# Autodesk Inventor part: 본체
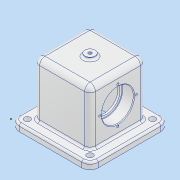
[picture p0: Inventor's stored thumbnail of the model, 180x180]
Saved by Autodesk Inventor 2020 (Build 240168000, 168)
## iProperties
Created: 2022-07
Part Number: 본체
Material: 알루미늄 6061
Document SubType Name: Modeling
Designer: MIRAE
Density: 2.7 g/cm^3
Appearance: 알루미늄 - 평지
Mass: 1059.83 g
Surface Area: 721.846 cm^2
Volume: 392.53 cm^3
Author: MIRAE
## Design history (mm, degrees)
sketch "스케치1"
  geometry: L1 (0, 0)-(-116, 0); L2 (-116, 0)-(-116, -116); L3 (-116, -116)-(0, -116); L4 (0, -116)-(0, 0)
  constraints: 8 end point, 2 parallel, 1 horizontal, 1 perpendicular
  dimensions: "d0" = 116 distance of L2.end L3.end; "d1" = 116 distance of L1.end L2.end
extrude "돌출1" new body sketch "스케치1" distance "d2" = 10; taper "d3" = 0 deg
sketch "스케치2"
  geometry: L1 (0, 116)-(0, 0) reference; L2 (0, 58)-(116, 58) reference; L3 (116, 0)-(116, 116) reference; L4 (58, 116)-(58, 0) reference; L5 (17, 99)-(99, 99); L6 (99, 99)-(99, 17); L7 (99, 17)-(17, 17); L8 (17, 17)-(17, 99); L9 (17, 99)-(99, 17); L10 (99, 99)-(17, 17); 2 further points
  constraints: 16 end point, 6 midpoint, 2 horizontal, 2 parallel, 2 vertical, 1 perpendicular, 1 other
  dimensions: "d4" = 82 distance of L5.start L5.end; "d5" = 82 distance of L5.end L6.end
extrude "돌출2" join sketch "스케치2" distance "d6" = 80; taper "d7" = 0 deg
sketch "스케치3"
  geometry: L1 (116, -116)-(0, -116) reference; L2 (58, -116)-(58, 0) reference; L3 (0, 0)-(116, 0) reference; L4 (116, -58)-(0, -58) reference; L5 (79, -88)-(37, -88); L6 (37, -88)-(37, -28); L7 (37, -28)-(79, -28); L8 (79, -28)-(79, -88); L9 (79, -88)-(37, -28); L10 (37, -88)-(79, -28); 2 further points
  constraints: 16 end point, 6 midpoint, 3 horizontal, 2 parallel, 1 perpendicular, 1 vertical, 1 other
  dimensions: "d8" = 42 distance of L5.start L5.end; "d9" = 60 distance of L5.end L6.end
extrude "돌출3" cut sketch "스케치3" distance "d10" = 80; taper "d11" = 0 deg
node "작업 평면1"
sketch "스케치4"
  geometry: L1 (17, 10)-(17, 90); L2 (0, 0)-(116, 0) reference; L3 (17, 48)-(99, 48); L4 (99, 10)-(99, 90); L5 (17, 48)-(34, 48); L6 (34, 48)-(34, 71.5); L7 (34, 71.5)-(17, 71.5); L8 (17, 71.5)-(17, 48); L9 (34, 48)-(38.895, 48); L10 (34, 67.956)-(34, 48); L11 (37, 0)-(37, 80) reference; L12 (34, 48)-(37, 48); L13 (37, 48)-(37, 68); L14 (37, 68)-(34, 68); L15 (34, 68)-(34, 48); L16 (79, 80)-(37, 80) reference; L17 (58, 80)-(58, 48); L18 (82, 71.5)-(99, 71.5); L19 (82, 67.956)-(82, 48); L20 (82, 48)-(82, 71.5); L21 (79, 68)-(82, 68); L22 (79, 0)-(79, 80); 6 further points
  constraints: 38 end point, 7 symmetric about line, 4 point on line, 2 horizontal, 2 midpoint, 2 parallel, 1 perpendicular
  dimensions: "d14" = 48 distance between parallel lines of L2 L3; "d15" = 17 distance of L6.end L7.end; "d17" = 40 diameter of L14 L3; "d18" = 47 diameter of L7 L3
revolve "회전1" sketch "스케치4" stored, may be unused: angle "d19" = 90 deg
fillet "모깎기1" dims "d20" = 8
fillet "모깎기2" dims "d21" = 8
chamfer "모따기1" distance "d22" = 1; stored, may be unused: second distance "d23" = 2, angle "d24" = 45 deg
chamfer "모따기2" distance "d25" = 1; stored, may be unused: second distance "d26" = 2, angle "d27" = 45 deg
sketch "스케치5" dims "d28" = 54
  geometry: C1 r 20 at (33, 38) reference; 3 further points
  constraints: 1 coincident, 1 vertical alignment, 2 other
hole "구멍1" sketch "스케치5" at (33, 65) diameter "d29" = 3.242; stored, may be unused: countersink angle "d33" = 90 deg, drill point angle "d35" = 118 deg; dims "d30" = 8, "d31" = 4, "d32" = 2, "d34" = 10
node "작업 평면2"
sketch "스케치6"
  geometry: 1 further point
fillet "모깎기3" dims "d40" = 12
sketch "스케치7"
  geometry: A1 r 12 centre (12, 12) between (0, 12) and (12, 0) reference; A2 r 12 centre (12, 104) between (12, 116) and (0, 104) reference; A3 r 12 centre (104, 104) between (116, 104) and (104, 116) reference; A4 r 12 centre (104, 12) between (104, 0) and (116, 12) reference; 5 further points
  constraints: 4 coincident
hole "구멍2" sketch "스케치7" at (12, 12), (12, 104), (104, 104), (104, 12) diameter "d41" = 9; stored, may be unused: countersink angle "d45" = 90 deg, drill point angle "d47" = 0 deg; dims "d42" = 8, "d43" = 4, "d44" = 2, "d46" = 10
sketch "스케치8"
  geometry: L1 (25, 17)-(91, 17) reference; L2 (58, 17)-(58, 99); L3 (91, 99)-(25, 99) reference; C1 r 7.5 at (58, 58); 1 further point
  constraints: 3 midpoint, 2 end point, 1 centre point
  dimensions: "d48" = 15 diameter of C1
extrude "돌출4" join sketch "스케치8" distance "d49" = 4; taper "d50" = 0 deg
fillet "모깎기4" dims "d51" = 3
sketch "스케치9"
  geometry: 2 further points
hole "구멍3" sketch "스케치9" at (0, 0) diameter "d52" = 4.917; stored, may be unused: countersink angle "d56" = 90 deg, drill point angle "d58" = 0 deg; dims "d53" = 14, "d54" = 4, "d55" = 2, "d57" = 17.1
node "작업 평면3"
sketch "스케치10"
  geometry: L1 (-13, -10)-(79, -10) reference; 3 further points
  constraints: 1 midpoint, 1 vertical alignment, 1 other
  dimensions: "d60" = 48 distance from line of L1 point (33, 38)
feature "엠보싱1" sketch "스케치10" dims "d0" = 116, "d1" = 116, "d61" = 0.5, "d62" = 0
fillet "모깎기5" dims "d63" = 0.6
fillet "모깎기6" dims "d64" = 3
fillet "모깎기7" dims "d65" = 3
node "솔리드1"
pattern_circular "원형 패턴1" dims angle "d37" = 360 deg
mirror "미러1"
feature "A9D066F2-1C7D-4E18-AEED-F7BC21143FA4" dims "d41" = 9, "d42" = 8, "d43" = 4, "d44" = 2, "d45" = 90 deg, "d46" = 10, "d47" = 0
other parameters: "d12" = -58, "d39" = 58
